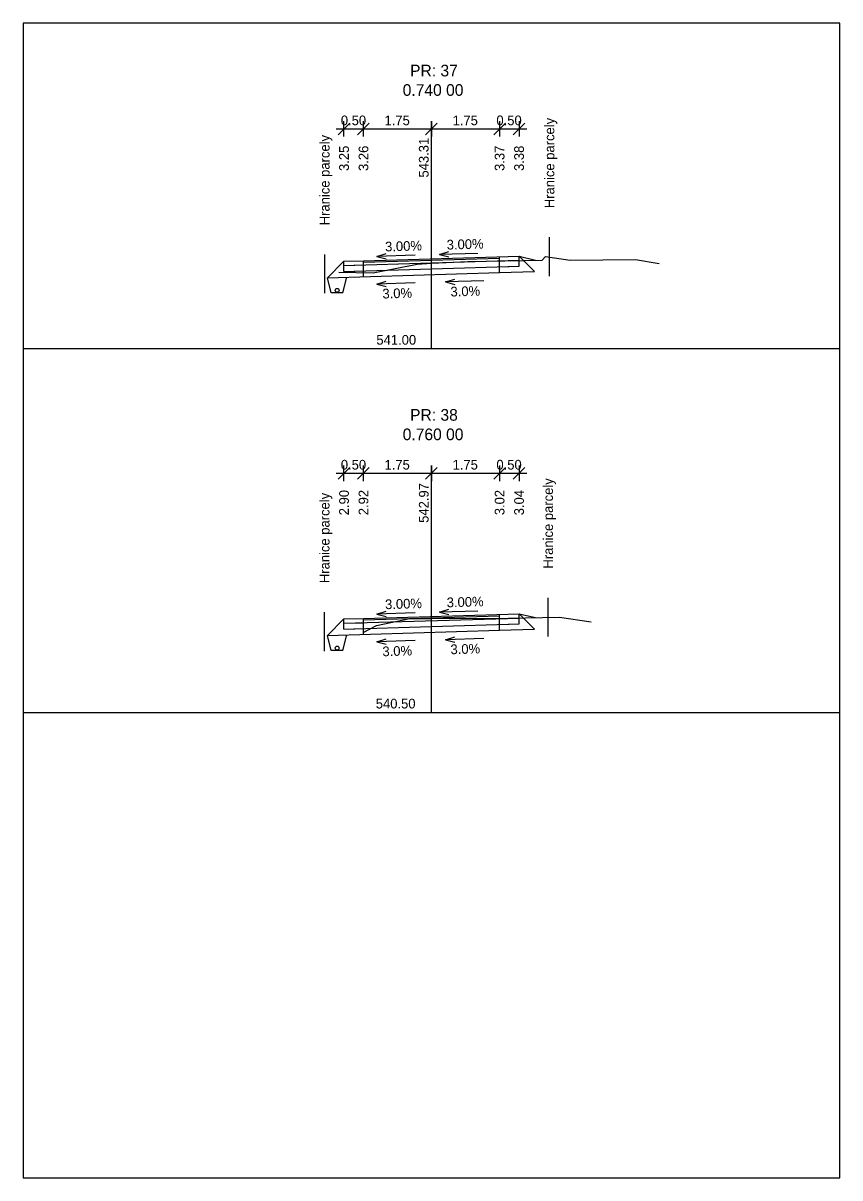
# Model space of a CAD drawing. Extents: x -603737 to -603383, y -1112154 to -1112124.
# Drawn here: x -603404.22 to -603383.22, y -1112153.84 to -1112124.14 of the extents above; entities that cross this region are included whole.
import ezdxf

# ---------------------------------------------------------------- set-up
doc = ezdxf.new("R2010")
doc.units = 0
for name, color, linetype in [('_křivky z hran', 7, 'Continuous'), ('_netisk', 7, 'Continuous'), ('C3D_Podsestava-Popis', 7, 'Continuous'), ('C3D_PP-Popisek', 7, 'Continuous'), ('C3D_PR', 7, 'Continuous'), ('C3D_ZPR', 7, 'Continuous'), ('Default', 7, 'Continuous'), ('konstrukce', 7, 'Continuous')]:
    doc.layers.add(name, color=color, linetype=linetype)

# ---------------------------------------------------------------- blocks, each defined once
blk = doc.blocks.new('_Oblique')
at = {"layer": 'Default'}
blk.add_line((-0.5, -0.5), (0.5, 0.5), dxfattribs=at)
blk = doc.blocks.new('AeccTickLine')
at = {"layer": 'Default'}
blk.add_line((0, 1), (0, -1), dxfattribs=at)

msp = doc.modelspace()

# ---------------------------------------------------------------- linework, layer by layer
at = {"layer": '_netisk'}
msp.add_lwpolyline([(-603404.218, -1112153.84), (-603383.218, -1112153.84), (-603383.218, -1112124.14), (-603404.218, -1112124.14)], close=True, dxfattribs=at)
at = {"layer": 'C3D_Podsestava-Popis'}
for p, q in [((-603396.168, -1112126.861), (-603393.718, -1112126.861)), ((-603393.718, -1112126.861), (-603391.268, -1112126.861)), ((-603393.718, -1112128.198), (-603393.718, -1112127.011)), ((-603396.168, -1112135.717), (-603393.718, -1112135.717)), ((-603393.718, -1112135.717), (-603391.268, -1112135.717)), ((-603393.718, -1112137.398), (-603393.718, -1112135.867))]:
    msp.add_line(p, q, dxfattribs=at)
at = {"layer": 'C3D_PP-Popisek'}
for p, q in [((-603395.121, -1112130.14), (-603394.884, -1112130.065)), ((-603394.137, -1112130.111), (-603395.121, -1112130.14)), ((-603395.121, -1112130.14), (-603394.88, -1112130.201)), ((-603393.51, -1112130.092), (-603393.273, -1112130.016)), ((-603392.526, -1112130.062), (-603393.51, -1112130.092)), ((-603393.51, -1112130.092), (-603393.269, -1112130.153)), ((-603393.356, -1112130.798), (-603393.12, -1112130.722)), ((-603395.121, -1112130.851), (-603394.884, -1112130.775)), ((-603394.137, -1112130.821), (-603395.121, -1112130.851)), ((-603395.121, -1112130.851), (-603394.88, -1112130.912)), ((-603392.373, -1112130.768), (-603393.356, -1112130.798)), ((-603393.356, -1112130.798), (-603393.116, -1112130.859)), ((-603395.121, -1112139.34), (-603394.884, -1112139.265)), ((-603394.137, -1112139.311), (-603395.121, -1112139.34)), ((-603395.121, -1112139.34), (-603394.88, -1112139.402)), ((-603393.51, -1112139.292), (-603393.273, -1112139.217)), ((-603392.526, -1112139.262), (-603393.51, -1112139.292)), ((-603393.51, -1112139.292), (-603393.269, -1112139.353)), ((-603393.356, -1112139.998), (-603393.12, -1112139.922)), ((-603395.121, -1112140.051), (-603394.884, -1112139.975)), ((-603394.137, -1112140.021), (-603395.121, -1112140.051)), ((-603395.121, -1112140.051), (-603394.88, -1112140.112)), ((-603392.373, -1112139.968), (-603393.356, -1112139.998)), ((-603393.356, -1112139.998), (-603393.116, -1112140.059))]:
    msp.add_line(p, q, dxfattribs=at)
at = {"layer": 'C3D_PR'}
for points in [[(-603396.103, -1112130.549), (-603395.215, -1112130.567), (-603394.089, -1112130.337), (-603393.718, -1112130.318), (-603392.785, -1112130.273), (-603390.874, -1112130.234), (-603390.788, -1112130.147), (-603390.152, -1112130.236), (-603388.473, -1112130.216), (-603387.867, -1112130.324)], [(-603395.479, -1112139.816), (-603395.13, -1112139.631), (-603394.271, -1112139.452), (-603393.718, -1112139.45), (-603391.739, -1112139.442), (-603390.427, -1112139.416), (-603389.611, -1112139.535)]]:
    msp.add_lwpolyline(points, dxfattribs=at)
at = {"layer": 'C3D_ZPR'}
for p, q in [((-603393.718, -1112132.511), (-603393.718, -1112127.011)), ((-603390.684, -1112130.65), (-603390.684, -1112129.65)), ((-603396.464, -1112131.09), (-603396.464, -1112130.09)), ((-603395.468, -1112130.251), (-603391.468, -1112130.131)), ((-603391.968, -1112130.186), (-603391.968, -1112130.146)), ((-603391.968, -1112130.556), (-603391.968, -1112130.146)), ((-603391.468, -1112130.391), (-603391.468, -1112130.131)), ((-603391.468, -1112130.391), (-603391.468, -1112130.131)), ((-603391.468, -1112130.131), (-603391.07, -1112130.529)), ((-603391.468, -1112130.131), (-603391.043, -1112130.237)), ((-603391.468, -1112130.131), (-603391.043, -1112130.237)), ((-603396.391, -1112130.689), (-603395.968, -1112130.266)), ((-603395.968, -1112130.376), (-603391.468, -1112130.241)), ((-603395.968, -1112130.266), (-603395.468, -1112130.251)), ((-603395.968, -1112130.526), (-603395.968, -1112130.266)), ((-603395.968, -1112130.526), (-603395.968, -1112130.266)), ((-603395.968, -1112130.376), (-603395.468, -1112130.361)), ((-603395.968, -1112130.526), (-603391.468, -1112130.391)), ((-603395.468, -1112130.291), (-603391.968, -1112130.186)), ((-603395.468, -1112130.661), (-603395.468, -1112130.251)), ((-603395.468, -1112130.361), (-603395.468, -1112130.291)), ((-603391.968, -1112130.256), (-603391.468, -1112130.241)), ((-603391.968, -1112130.406), (-603391.968, -1112130.256)), ((-603391.968, -1112130.406), (-603391.468, -1112130.391)), ((-603396.391, -1112130.689), (-603391.968, -1112130.556)), ((-603395.968, -1112130.526), (-603395.468, -1112130.511)), ((-603395.468, -1112130.661), (-603395.468, -1112130.511)), ((-603391.968, -1112130.556), (-603391.07, -1112130.529)), ((-603404.218, -1112132.511), (-603383.218, -1112132.511)), ((-603393.718, -1112141.867), (-603393.718, -1112135.867)), ((-603390.719, -1112139.919), (-603390.719, -1112138.919)), ((-603396.466, -1112140.294), (-603396.466, -1112139.294)), ((-603395.468, -1112139.451), (-603391.468, -1112139.331)), ((-603391.968, -1112139.386), (-603391.968, -1112139.346)), ((-603391.968, -1112139.756), (-603391.968, -1112139.346)), ((-603391.468, -1112139.591), (-603391.468, -1112139.331)), ((-603391.468, -1112139.591), (-603391.468, -1112139.331)), ((-603391.468, -1112139.331), (-603391.07, -1112139.729)), ((-603391.468, -1112139.331), (-603391.043, -1112139.428)), ((-603391.468, -1112139.331), (-603391.043, -1112139.428)), ((-603396.391, -1112139.889), (-603395.968, -1112139.466)), ((-603395.968, -1112139.576), (-603391.468, -1112139.441)), ((-603395.968, -1112139.466), (-603395.468, -1112139.451)), ((-603395.968, -1112139.726), (-603395.968, -1112139.466)), ((-603395.968, -1112139.726), (-603395.968, -1112139.466)), ((-603395.968, -1112139.576), (-603395.468, -1112139.561)), ((-603395.968, -1112139.726), (-603391.468, -1112139.591)), ((-603395.468, -1112139.491), (-603391.968, -1112139.386)), ((-603395.468, -1112139.861), (-603395.468, -1112139.451)), ((-603395.468, -1112139.561), (-603395.468, -1112139.491)), ((-603391.968, -1112139.456), (-603391.468, -1112139.441)), ((-603391.968, -1112139.606), (-603391.968, -1112139.456)), ((-603391.968, -1112139.606), (-603391.468, -1112139.591)), ((-603396.391, -1112139.889), (-603391.968, -1112139.756)), ((-603395.968, -1112139.726), (-603395.468, -1112139.711)), ((-603395.468, -1112139.861), (-603395.468, -1112139.711)), ((-603391.968, -1112139.756), (-603391.07, -1112139.729)), ((-603404.218, -1112141.867), (-603383.218, -1112141.867))]:
    msp.add_line(p, q, dxfattribs=at)
at = {"layer": 'konstrukce'}
for p, q in [((-603396.294, -1112131.074), (-603396.391, -1112130.689)), ((-603395.994, -1112131.074), (-603395.894, -1112130.674)), ((-603395.994, -1112131.074), (-603396.294, -1112131.074)), ((-603396.294, -1112140.274), (-603396.391, -1112139.889)), ((-603395.994, -1112140.274), (-603395.894, -1112139.874)), ((-603395.994, -1112140.274), (-603396.294, -1112140.274))]:
    msp.add_line(p, q, dxfattribs=at)
for centre in [(-603396.144, -1112131.014), (-603396.144, -1112140.214)]:
    msp.add_circle(centre, 0.05, dxfattribs=at)

# ---------------------------------------------------------------- block references
at = {"layer": '_křivky z hran', "rotation": 180}
for name, p, xscale, yscale in [('_Oblique', (-603395.968, -1112126.861), 0.3, 0.3), ('AeccTickLine', (-603395.968, -1112126.861), 0.2, 0.20000000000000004), ('_Oblique', (-603395.468, -1112126.861), 0.3, 0.3), ('AeccTickLine', (-603395.468, -1112126.861), 0.2, 0.20000000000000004), ('_Oblique', (-603393.718, -1112126.861), 0.3, 0.3), ('AeccTickLine', (-603393.718, -1112126.861), 0.2, 0.20000000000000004), ('_Oblique', (-603395.968, -1112135.717), 0.3, 0.3), ('AeccTickLine', (-603395.968, -1112135.717), 0.2, 0.20000000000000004), ('_Oblique', (-603395.468, -1112135.717), 0.3, 0.3), ('AeccTickLine', (-603395.468, -1112135.717), 0.2, 0.20000000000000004), ('_Oblique', (-603393.718, -1112135.717), 0.3, 0.3), ('AeccTickLine', (-603393.718, -1112135.717), 0.2, 0.20000000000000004)]:
    msp.add_blockref(name, p, dxfattribs=dict(at, xscale=xscale, yscale=yscale))
at = {"layer": '_křivky z hran'}
for name, p, xscale, yscale in [('_Oblique', (-603393.718, -1112126.861), 0.3, 0.3), ('AeccTickLine', (-603393.718, -1112126.861), 0.2, 0.20000000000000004), ('_Oblique', (-603391.968, -1112126.861), 0.3, 0.3), ('AeccTickLine', (-603391.968, -1112126.861), 0.2, 0.20000000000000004), ('_Oblique', (-603391.468, -1112126.861), 0.3, 0.3), ('AeccTickLine', (-603391.468, -1112126.861), 0.2, 0.20000000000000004), ('_Oblique', (-603393.718, -1112135.717), 0.3, 0.3), ('AeccTickLine', (-603393.718, -1112135.717), 0.2, 0.20000000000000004), ('_Oblique', (-603391.968, -1112135.717), 0.3, 0.3), ('AeccTickLine', (-603391.968, -1112135.717), 0.2, 0.20000000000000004), ('_Oblique', (-603391.468, -1112135.717), 0.3, 0.3), ('AeccTickLine', (-603391.468, -1112135.717), 0.2, 0.20000000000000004)]:
    msp.add_blockref(name, p, dxfattribs=dict(at, xscale=xscale, yscale=yscale))

# ---------------------------------------------------------------- texts
at = {"layer": 'C3D_Podsestava-Popis'}
for s, rotation, p in [('0.50', 360, (-603396.049, -1112126.767)), ('1.75', 360, (-603394.926, -1112126.767)), ('1.75', 360, (-603394.926, -1112126.767)), ('1.75', 360, (-603393.176, -1112126.767)), ('1.75', 360, (-603393.176, -1112126.767)), ('0.50', 360, (-603392.049, -1112126.767)), ('543.31', 90, (-603393.792, -1112128.113)), ('3.25', 90, (-603395.842, -1112127.944)), ('3.26', 90, (-603395.342, -1112127.943)), ('3.37', 90, (-603391.842, -1112127.943)), ('3.38', 90, (-603391.342, -1112127.943)), ('3.38', 90, (-603391.342, -1112127.943)), ('3.00%', 1.7184, (-603394.908, -1112130.014)), ('3.00%', 1.7184, (-603393.323, -1112129.966)), ('3.0%', 1.7184, (-603394.976, -1112131.225)), ('3.0%', 1.7184, (-603393.226, -1112131.173)), ('0.50', 360, (-603396.049, -1112135.623)), ('1.75', 360, (-603394.926, -1112135.623)), ('1.75', 360, (-603394.926, -1112135.623)), ('1.75', 360, (-603393.176, -1112135.623)), ('1.75', 360, (-603393.176, -1112135.623)), ('0.50', 360, (-603392.049, -1112135.623)), ('542.97', 90, (-603393.792, -1112136.993)), ('2.90', 90, (-603395.842, -1112136.798)), ('2.92', 90, (-603395.342, -1112136.797)), ('3.02', 90, (-603391.842, -1112136.797)), ('3.04', 90, (-603391.342, -1112136.798)), ('3.04', 90, (-603391.342, -1112136.798)), ('3.00%', 1.7184, (-603394.908, -1112139.214)), ('3.00%', 1.7184, (-603393.323, -1112139.166)), ('3.0%', 1.7184, (-603394.976, -1112140.425)), ('3.0%', 1.7184, (-603393.226, -1112140.373))]:
    msp.add_text(s, height=0.25, rotation=rotation, dxfattribs=at).set_placement(p)
at = {"layer": 'C3D_ZPR'}
for s, p in [('PR: 37', (-603394.268, -1112125.511)), ('0.740 00', (-603394.458, -1112126.011)), ('PR: 38', (-603394.268, -1112134.367)), ('0.760 00', (-603394.458, -1112134.867))]:
    msp.add_text(s, height=0.3, dxfattribs=at).set_placement(p)
for s, rotation, p in [('Hranice parcely', 90, (-603390.559, -1112128.9)), ('Hranice parcely', 90, (-603396.339, -1112129.34)), ('541.00', 360, (-603395.135, -1112132.411)), ('Hranice parcely', 90, (-603390.594, -1112138.169)), ('Hranice parcely', 90, (-603396.341, -1112138.544)), ('540.50', 360, (-603395.151, -1112141.767))]:
    msp.add_text(s, height=0.25, rotation=rotation, dxfattribs=at).set_placement(p)

doc.saveas('drawing.dxf')
